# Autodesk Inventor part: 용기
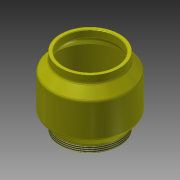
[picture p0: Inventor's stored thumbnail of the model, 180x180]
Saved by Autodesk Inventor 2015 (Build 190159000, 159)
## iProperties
Created: 2018-01
Part Number: 용기
Material: ABS 플라스틱
Document SubType Name: Modeling
Designer: mduedu
Density: 1 g/cm^3
Appearance: 노란색
Author: mduedu
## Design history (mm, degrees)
sketch "스케치1"
  geometry: L1 (0, 0)-(-35, 0); L2 (-35, 0)-(-35, 9); L3 (-35, 9)-(-45, 20); L4 (-45, 20)-(-45, 60); L5 (-45, 60)-(-35, 71); L6 (-35, 71)-(-35, 80); L7 (-35, 80)-(0, 80); L8 (0, 80)-(0, 0)
  constraints: 16 end point, 3 collinear, 3 parallel, 1 horizontal, 1 perpendicular
  dimensions: "d0" = 9 distance of L1.end L2.end; "d2" = 70 diameter of L2 L8; "d3" = 20 distance from line of L3.end L1; "d4" = 60 distance from line of L4.end L1; "d5" = 20 distance from line of L4.end L7; "d6" = 90 diameter of L4 L8
revolve "회전1" sketch "스케치1" stored, may be unused: angle "d7" = 90 deg
fillet "모깎기1" dims "d8" = 3
feature "쉘1" dims "d9" = 4
chamfer "모따기1" distance "d11" = 0.5; stored, may be unused: second distance "d12" = 2, angle "d13" = 45 deg
feature "스레드1" dims "d14" = 7, "d15" = 0
node "솔리드1"
